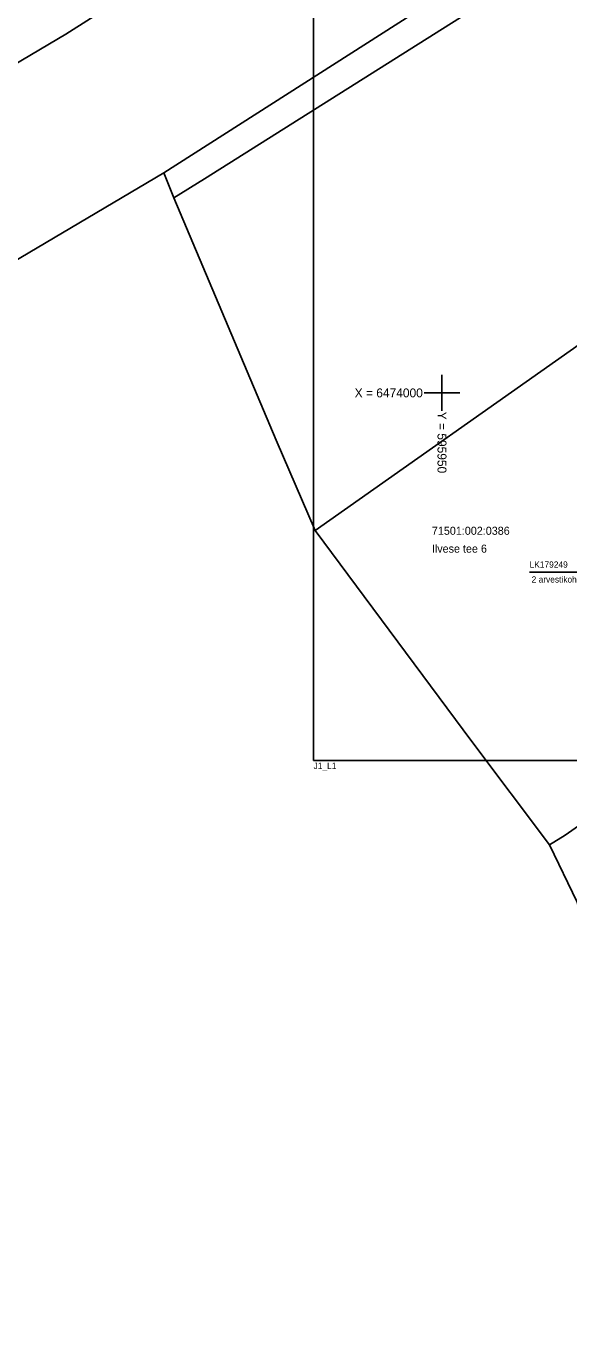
# Model space of a CAD drawing. Extents: x 593727 to 603084, y 6472047 to 6482364.
# Drawn here: x 595903.5 to 595964.2, y 6473893.6 to 6474041 of the extents above; entities that cross this region are included whole.
import ezdxf

# ---------------------------------------------------------------- set-up
doc = ezdxf.new("R2010")
doc.units = 0
for name, color, linetype in [('ELRAJATISMP', 7, 'Continuous'), ('PIIR', 7, 'Continuous'), ('VORK', 7, 'Continuous'), ('VORMISTUS', 7, 'Continuous')]:
    doc.layers.add(name, color=color, linetype=linetype)

msp = doc.modelspace()

# ---------------------------------------------------------------- linework, layer by layer
at = {"layer": 'ELRAJATISMP'}
msp.add_lwpolyline([(595988.83, 6473975.08), (595979.51, 6473979.96), (595959.79, 6473979.96)], dxfattribs=at)
at = {"layer": 'PIIR'}
for points in [[(595163.63, 6473530.56), (595305.16, 6473633.25), (595494.14, 6473772.49), (595697.24, 6473927.6), (595708.17, 6473927.27), (595715.6, 6473927.51), (595750.33, 6473946.74), (595907.95, 6474040.11), (595994.93, 6474095.35), (596020.12, 6474113.41), (596019.32, 6474114.18), (596044.59, 6474133.13), (596093.67, 6474173.19), (596278.62, 6474335.15), (596535.51, 6474560.32), (596655.01, 6474673.01), (596739.82, 6474757.12), (596825.19, 6474841.82)], [(596840.06, 6474826.17), (596697.33, 6474679.08), (596629.71, 6474613.93), (596561.95, 6474539.93), (596573.04, 6474527.95), (596298.85, 6474323.82), (596108.16, 6474156.64), (596058.46, 6474116.05), (596034.96, 6474098.69), (596033.85, 6474099.72), (596007.79, 6474081.36), (595918.92, 6474024.6), (595757.48, 6473929.02), (595757.75, 6473927.63), (595712.46, 6473902.51), (595641.49, 6473857.12), (595540.92, 6473781.82), (595525.42, 6473769.26), (595508.5, 6473755.83), (595319.98, 6473616.99), (595177.03, 6473513.11)], [(595974.94, 6474056.4), (595923.45, 6474023.94), (595920.02, 6474021.81), (595918.92, 6474024.6), (596007.79, 6474081.36)]]:
    msp.add_lwpolyline(points, dxfattribs=at)
for points in [[(595920.02, 6474021.81), (595923.45, 6474023.94), (595974.94, 6474056.4), (595995.81, 6474026.85), (595965.97, 6474005.85), (595935.81, 6473984.63), (595931.46, 6473994.7)], [(595935.81, 6473984.63), (595965.97, 6474005.85), (595987.85, 6473974.77), (595991.31, 6473969.86), (595963.77, 6473950.58), (595962.03, 6473949.48), (595953.34, 6473961.05)], [(595962.03, 6473949.48), (595963.77, 6473950.58), (595991.31, 6473969.86), (595994.75, 6473964.97), (596016.68, 6473934.04), (595975.1, 6473904.62), (595970.53, 6473901.86), (595972.52, 6473915.54), (595965.11, 6473943.08)]]:
    msp.add_lwpolyline(points, close=True, dxfattribs=at)
at = {"layer": 'VORK'}
for p, q in [((595950, 6474002), (595950, 6473998)), ((595948, 6474000), (595952, 6474000))]:
    msp.add_line(p, q, dxfattribs=at)
at = {"layer": 'VORMISTUS'}
msp.add_lwpolyline([(595935.65, 6473958.91), (595935.65, 6474102.41), (596133.15, 6474102.41), (596133.15, 6473958.91)], close=True, dxfattribs=at)

# ---------------------------------------------------------------- texts
at = {"layer": 'ELRAJATISMP'}
for s, p in [('LK179249', (595959.79, 6473980.46)), ('2 arvestikohta; Harju Elekter, HETR 55L, 100A', (595960.02, 6473978.8))]:
    msp.add_text(s, height=0.7, dxfattribs=at).set_placement(p)
at = {"layer": 'PIIR'}
for s, p in [('71501:002:0386', (595948.87, 6473984.14)), ('Ilvese tee 6', (595948.87, 6473982.14))]:
    msp.add_text(s, height=0.9, dxfattribs=at).set_placement(p)
at = {"layer": 'VORK'}
msp.add_text('X = 6474000', height=1, dxfattribs=at).set_placement((595940.24, 6473999.5))
msp.add_text('Y = 595950 ', height=1, rotation=270, dxfattribs=at).set_placement((595949.5, 6473997.9))
at = {"layer": 'VORMISTUS'}
msp.add_text('J1_L1', height=0.7, dxfattribs=at).set_placement((595935.65, 6473957.96))

doc.saveas('drawing.dxf')
